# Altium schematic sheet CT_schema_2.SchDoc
size 316 x 200 mm
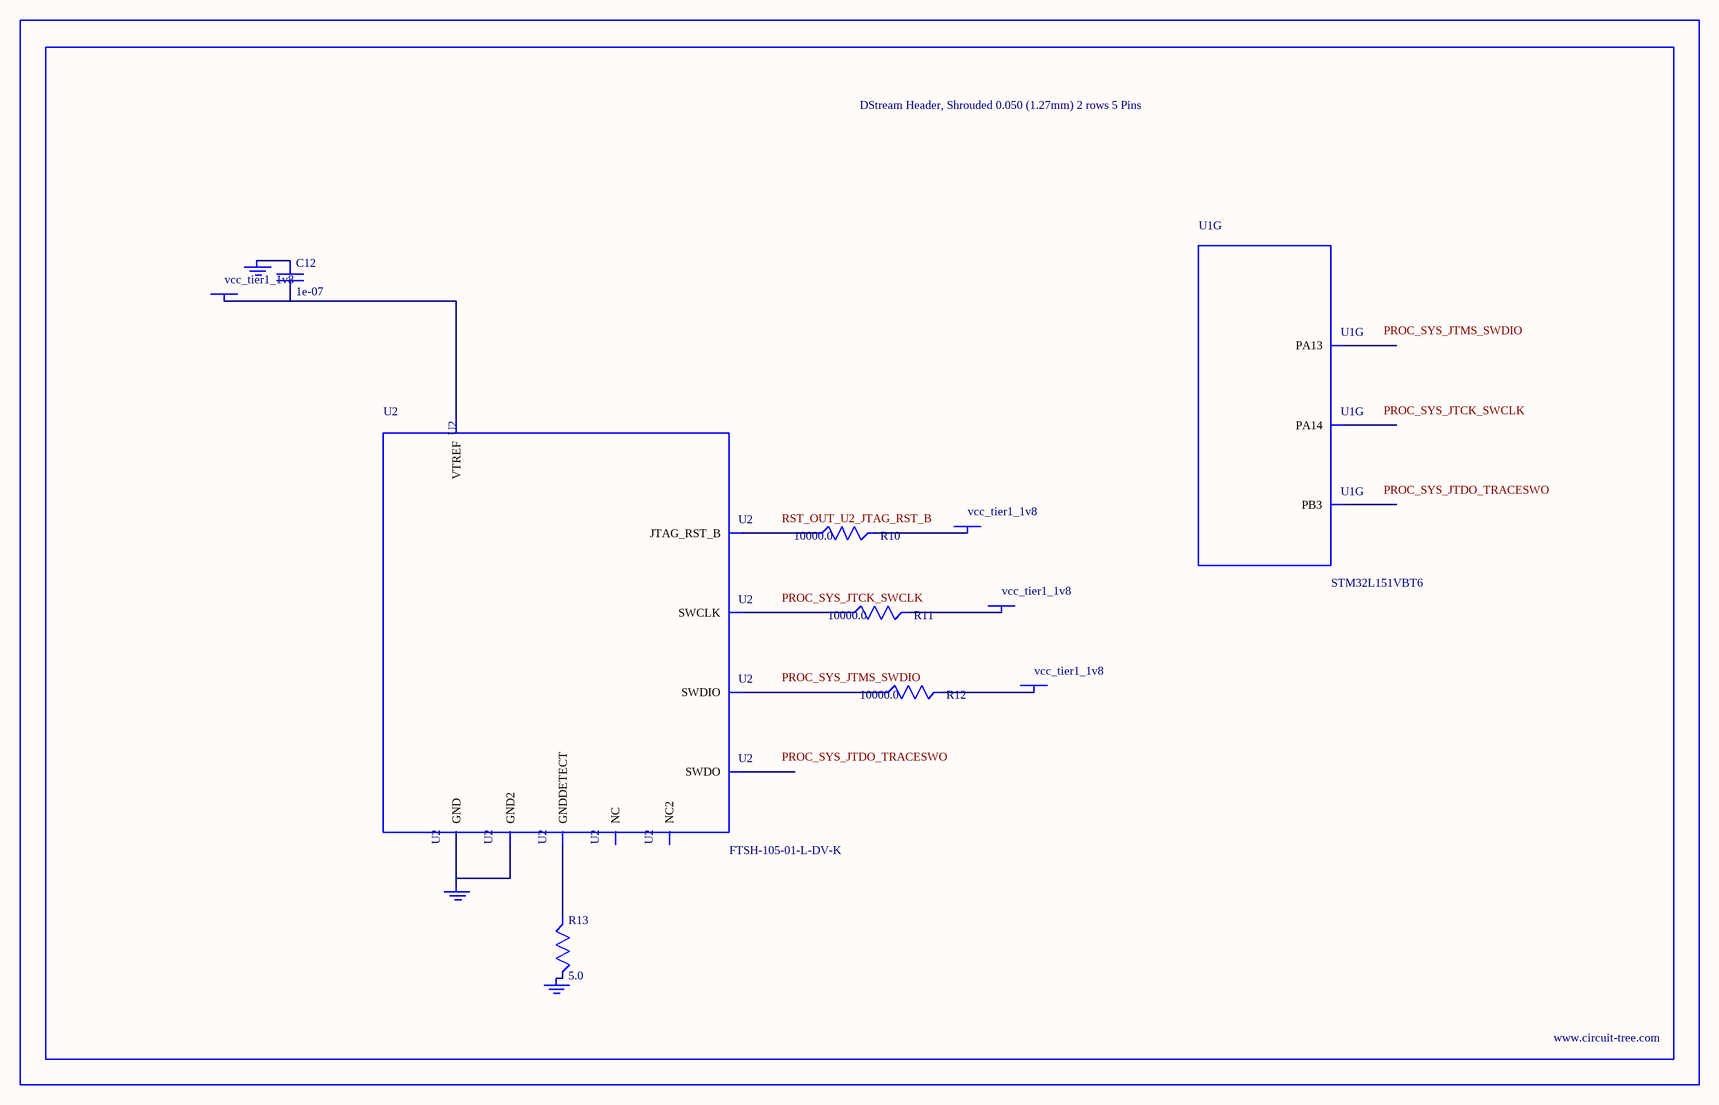
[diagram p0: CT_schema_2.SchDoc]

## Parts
BORDER1  (no value)
C12  1e-07  [C0402]
GND_INSTANCE_1_0  (no value)
GND_INSTANCE_1_1  (no value)
GND_INSTANCE_1_2  (no value)
POWER_INSTANCE_1_0  vcc_tier1_1v8
POWER_INSTANCE_1_1  vcc_tier1_1v8
POWER_INSTANCE_1_2  vcc_tier1_1v8
POWER_INSTANCE_1_3  vcc_tier1_1v8
R10  10000.0  [R0603]
R11  10000.0  [R0603]
R12  10000.0  [R0603]
R13  5.0  [R0603]
U1  STM32L151VBT6  [LQFP100]  (part G of 11)
U2  FTSH-105-01-L-DV-K  [SAMTEC_FTSH-105-01-L-DV-K]

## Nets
NetC12_1: C12.1 GND_INSTANCE_1_0.0(GND)
NetC12_2: C12.2 POWER_INSTANCE_1_0.0(PWR) U2.1(VTREF)
NetGND_INSTANCE_1_1_0: GND_INSTANCE_1_1.0(GND) R13.2
NetGND_INSTANCE_1_2_0: GND_INSTANCE_1_2.0(GND) U2.3(GND) U2.5(GND2)
NetPOWER_INSTANCE_1_1_0: POWER_INSTANCE_1_1.0(PWR) R12.2
NetPOWER_INSTANCE_1_2_0: POWER_INSTANCE_1_2.0(PWR) R11.2
NetPOWER_INSTANCE_1_3_0: POWER_INSTANCE_1_3.0(PWR) R10.2
NetR10_1: R10.1 U2.10(JTAG_RST_B)
NetR11_1: R11.1 U2.4(SWCLK)
NetR12_1: R12.1 U2.2(SWDIO)
NetR13_1: R13.1 U2.9(GNDDETECT)

Not connected (* = marked no-connect by the designer): U1 72(PA13) 76(PA14) 89(PB3); U2 6(SWDO) 7(NC) 8(NC2)

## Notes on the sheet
- Labels drawn without touching a wire or pin: PROC_SYS_JTCK_SWCLK, PROC_SYS_JTDO_TRACESWO, PROC_SYS_JTMS_SWDIO, RST_OUT_U2_JTAG_RST_B

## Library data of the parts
BORDER1 = BORDER_PAGE1
C12 = C0402C104K3RACTU
GND_INSTANCE_1_0-GND_INSTANCE_1_2 = GND
POWER_INSTANCE_1_0-POWER_INSTANCE_1_3 = PWR
R10-R12 = RC0603JR-0710KL
R13 = ERJ-3GEYJ5R1V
